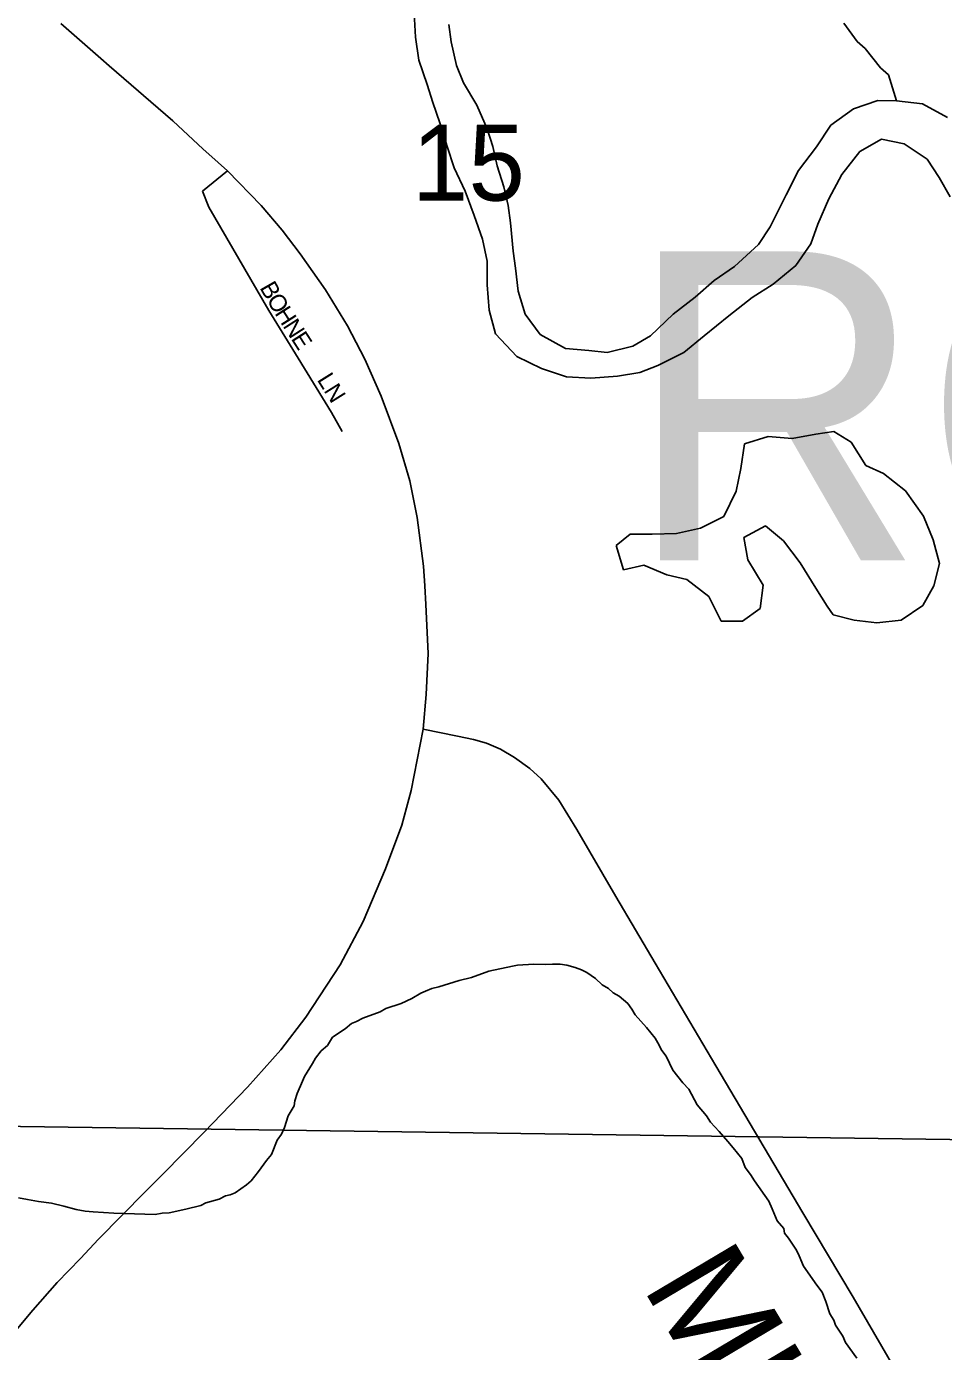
# Model space of a CAD drawing. Extents: x 0 to 34, y -2.3 to 22.
# Drawn here: x 5.851 to 6.357, y 17.221 to 17.952 of the extents above; entities that cross this region are included whole.
import ezdxf

# ---------------------------------------------------------------- set-up
doc = ezdxf.new("R2010")
doc.units = 0
for name, color, linetype in [('GM_X_Major_River', 7, 'Continuous'), ('GM_X_Minor_Lake', 7, 'Continuous'), ('GM_X_Minor_River', 7, 'Continuous'), ('GM_X_Section', 7, 'Continuous'), ('GM_X_Section_Text', 7, 'Continuous'), ('GM_X_Township_Road', 7, 'Continuous'), ('GM_X_Township_Road_Text', 7, 'Continuous'), ('GM_X_Township_Subdivision', 7, 'Continuous'), ('GM_X_Township_Subdivision_Text', 7, 'Continuous'), ('GM_X_Township_Text', 7, 'Continuous'), ('GM_X_US_Route', 7, 'Continuous')]:
    doc.layers.add(name, color=color, linetype=linetype)

msp = doc.modelspace()

# ---------------------------------------------------------------- linework, layer by layer
at = {"layer": 'GM_X_Major_River'}
for p, q in [((6.06492, 17.95936), (6.06566, 17.94603)), ((6.08535, 17.94355), (6.08411, 17.9531)), ((6.06566, 17.94603), (6.06757, 17.93343)), ((6.08839, 17.93053), (6.08535, 17.94355)), ((6.06757, 17.93343), (6.07212, 17.91998)), ((6.09228, 17.92091), (6.08839, 17.93053)), ((6.07212, 17.91998), (6.07524, 17.91001)), ((6.09952, 17.90853), (6.09228, 17.92091)), ((6.07524, 17.91001), (6.07909, 17.89887)), ((6.10521, 17.89544), (6.09952, 17.90853)), ((6.32076, 17.91117), (6.30732, 17.90662)), ((6.33101, 17.91087), (6.32076, 17.91117)), ((6.3454, 17.90931), (6.33101, 17.91087)), ((6.35924, 17.90167), (6.3454, 17.90931)), ((6.30732, 17.90662), (6.29489, 17.89748)), ((6.07909, 17.89887), (6.08327, 17.88582)), ((6.10835, 17.88584), (6.10521, 17.89544)), ((6.29489, 17.89748), (6.28694, 17.88554)), ((6.31081, 17.88294), (6.32279, 17.88982)), ((6.32279, 17.88982), (6.33525, 17.88717)), ((6.33525, 17.88717), (6.34793, 17.87881)), ((6.08327, 17.88582), (6.0871, 17.87392)), ((6.11069, 17.87512), (6.10835, 17.88584)), ((6.28694, 17.88554), (6.27706, 17.87252)), ((6.30093, 17.8703), (6.31081, 17.88294)), ((6.0871, 17.87392), (6.09318, 17.86119)), ((6.11453, 17.8636), (6.11069, 17.87512)), ((6.27706, 17.87252), (6.2702, 17.85904)), ((6.34793, 17.87881), (6.35447, 17.86873)), ((6.2937, 17.85682), (6.30093, 17.8703)), ((6.35447, 17.86873), (6.36061, 17.85791)), ((6.09318, 17.86119), (6.09811, 17.84774)), ((6.11689, 17.85327), (6.11453, 17.8636)), ((6.2702, 17.85904), (6.26132, 17.84142)), ((6.11813, 17.84373), (6.11689, 17.85327)), ((6.28759, 17.84293), (6.2937, 17.85682)), ((6.09811, 17.84774), (6.10266, 17.83467)), ((6.11957, 17.82809), (6.11813, 17.84373)), ((6.28385, 17.83202), (6.28759, 17.84293)), ((6.26132, 17.84142), (6.25496, 17.83172)), ((6.10266, 17.83467), (6.10534, 17.82242)), ((6.12081, 17.81855), (6.11957, 17.82809)), ((6.25496, 17.83172), (6.24168, 17.81957)), ((6.27551, 17.82009), (6.28385, 17.83202)), ((6.10534, 17.82242), (6.10534, 17.8095)), ((6.12233, 17.80596), (6.12081, 17.81855)), ((6.24168, 17.81957), (6.23043, 17.81191)), ((6.26305, 17.80981), (6.27551, 17.82009)), ((6.10534, 17.8095), (6.10644, 17.79539)), ((6.12614, 17.7933), (6.12233, 17.80596)), ((6.23043, 17.81191), (6.2199, 17.80271)), ((6.25144, 17.80255), (6.26305, 17.80981)), ((6.2199, 17.80271), (6.20784, 17.79318)), ((6.23859, 17.79228), (6.25144, 17.80255)), ((6.10644, 17.79539), (6.10986, 17.78236)), ((6.13455, 17.78202), (6.12614, 17.7933)), ((6.20784, 17.79318), (6.19533, 17.78138)), ((6.22497, 17.78127), (6.23859, 17.79228)), ((6.10986, 17.78236), (6.12165, 17.76985)), ((6.14838, 17.77439), (6.13455, 17.78202)), ((6.19533, 17.78138), (6.18566, 17.77558)), ((6.21368, 17.7721), (6.22497, 17.78127)), ((6.12165, 17.76985), (6.13514, 17.76337)), ((6.16127, 17.77325), (6.14838, 17.77439)), ((6.1715, 17.77219), (6.16127, 17.77325)), ((6.18566, 17.77558), (6.1715, 17.77219)), ((6.19941, 17.76491), (6.21368, 17.7721)), ((6.13514, 17.76337), (6.14906, 17.75878)), ((6.18941, 17.76102), (6.19941, 17.76491)), ((6.14906, 17.75878), (6.16234, 17.75801)), ((6.16234, 17.75801), (6.17719, 17.7591)), ((6.17719, 17.7591), (6.18941, 17.76102))]:
    msp.add_line(p, q, dxfattribs=at)
at = {"layer": 'GM_X_Minor_Lake'}
for p, q in [((6.26019, 17.72586), (6.24715, 17.72168)), ((6.27346, 17.72471), (6.26019, 17.72586)), ((6.28645, 17.72699), (6.27346, 17.72471)), ((6.29638, 17.7286), (6.28645, 17.72699)), ((6.30608, 17.72261), (6.29638, 17.7286)), ((6.24715, 17.72168), (6.24523, 17.70805)), ((6.31406, 17.70983), (6.30608, 17.72261)), ((6.24523, 17.70805), (6.24258, 17.69558)), ((6.32381, 17.70536), (6.31406, 17.70983)), ((6.33607, 17.69588), (6.32381, 17.70536)), ((6.24258, 17.69558), (6.23571, 17.68171)), ((6.34592, 17.6819), (6.33607, 17.69588)), ((6.23571, 17.68171), (6.22298, 17.67524)), ((6.35123, 17.66881), (6.34592, 17.6819)), ((6.22298, 17.67524), (6.20959, 17.67221)), ((6.24677, 17.66998), (6.25874, 17.67647)), ((6.25874, 17.67647), (6.26875, 17.66819)), ((6.18412, 17.67181), (6.17634, 17.66558)), ((6.19628, 17.67184), (6.18412, 17.67181)), ((6.20959, 17.67221), (6.19628, 17.67184)), ((6.24907, 17.65774), (6.24677, 17.66998)), ((6.26875, 17.66819), (6.2779, 17.65613)), ((6.35465, 17.65578), (6.35123, 17.66881)), ((6.17634, 17.66558), (6.1805, 17.65215)), ((6.1805, 17.65215), (6.1916, 17.65486)), ((6.1916, 17.65486), (6.20436, 17.64955)), ((6.25739, 17.64381), (6.24907, 17.65774)), ((6.2779, 17.65613), (6.28661, 17.64219)), ((6.35162, 17.64332), (6.35465, 17.65578)), ((6.20436, 17.64955), (6.21531, 17.64694)), ((6.21531, 17.64694), (6.22757, 17.63746)), ((6.25588, 17.63092), (6.25739, 17.64381)), ((6.28661, 17.64219), (6.29277, 17.63212)), ((6.3456, 17.63247), (6.35162, 17.64332)), ((6.22757, 17.63746), (6.23439, 17.62395)), ((6.24617, 17.62398), (6.25588, 17.63092)), ((6.29277, 17.63212), (6.29605, 17.62746)), ((6.33359, 17.62446), (6.3456, 17.63247)), ((6.23439, 17.62395), (6.24617, 17.62398)), ((6.29605, 17.62746), (6.30775, 17.62446)), ((6.30775, 17.62446), (6.32024, 17.62295)), ((6.32024, 17.62295), (6.33359, 17.62446))]:
    msp.add_line(p, q, dxfattribs=at)
at = {"layer": 'GM_X_Minor_River'}
for p, q in [((6.30935, 17.94367), (6.30204, 17.95376)), ((6.31379, 17.93973), (6.30935, 17.94367)), ((6.32223, 17.92922), (6.31379, 17.93973)), ((6.32668, 17.92529), (6.32223, 17.92922)), ((6.33101, 17.91087), (6.32668, 17.92529)), ((6.24715, 17.72168), (6.26019, 17.72586)), ((6.26019, 17.72586), (6.27346, 17.72471)), ((6.27346, 17.72471), (6.28645, 17.72699)), ((6.28645, 17.72699), (6.29638, 17.7286)), ((6.29638, 17.7286), (6.30608, 17.72261)), ((6.24523, 17.70805), (6.24715, 17.72168)), ((6.30608, 17.72261), (6.31406, 17.70983)), ((6.24258, 17.69558), (6.24523, 17.70805)), ((6.31406, 17.70983), (6.32381, 17.70536)), ((6.32381, 17.70536), (6.33607, 17.69588)), ((6.23571, 17.68171), (6.24258, 17.69558)), ((6.33607, 17.69588), (6.34592, 17.6819)), ((6.22298, 17.67524), (6.23571, 17.68171)), ((6.34592, 17.6819), (6.35123, 17.66881)), ((6.20959, 17.67221), (6.22298, 17.67524)), ((6.25874, 17.67647), (6.24677, 17.66998)), ((6.26875, 17.66819), (6.25874, 17.67647)), ((6.17634, 17.66558), (6.18412, 17.67181)), ((6.18412, 17.67181), (6.19628, 17.67184)), ((6.19628, 17.67184), (6.20959, 17.67221)), ((6.24677, 17.66998), (6.24907, 17.65774)), ((6.2779, 17.65613), (6.26875, 17.66819)), ((6.35123, 17.66881), (6.35465, 17.65578)), ((6.1805, 17.65215), (6.17634, 17.66558)), ((6.1916, 17.65486), (6.1805, 17.65215)), ((6.20436, 17.64955), (6.1916, 17.65486)), ((6.24907, 17.65774), (6.25739, 17.64381)), ((6.28661, 17.64219), (6.2779, 17.65613)), ((6.35465, 17.65578), (6.35162, 17.64332)), ((6.21531, 17.64694), (6.20436, 17.64955)), ((6.22757, 17.63746), (6.21531, 17.64694)), ((6.25739, 17.64381), (6.25588, 17.63092)), ((6.29277, 17.63212), (6.28661, 17.64219)), ((6.35162, 17.64332), (6.3456, 17.63247)), ((6.23439, 17.62395), (6.22757, 17.63746)), ((6.25588, 17.63092), (6.24617, 17.62398)), ((6.29605, 17.62746), (6.29277, 17.63212)), ((6.3456, 17.63247), (6.33359, 17.62446)), ((6.24617, 17.62398), (6.23439, 17.62395)), ((6.30775, 17.62446), (6.29605, 17.62746)), ((6.32024, 17.62295), (6.30775, 17.62446)), ((6.33359, 17.62446), (6.32024, 17.62295)), ((6.11924, 17.43353), (6.10624, 17.43088)), ((6.12192, 17.43421), (6.11924, 17.43353)), ((6.13106, 17.43469), (6.12192, 17.43421)), ((6.13751, 17.4345), (6.13106, 17.43469)), ((6.14132, 17.43476), (6.13751, 17.4345)), ((6.1455, 17.43464), (6.14132, 17.43476)), ((6.14928, 17.43414), (6.1455, 17.43464)), ((6.15381, 17.43287), (6.14928, 17.43414)), ((6.09663, 17.42736), (6.08974, 17.42567)), ((6.10624, 17.43088), (6.09663, 17.42736)), ((6.15719, 17.43163), (6.15381, 17.43287)), ((6.16019, 17.43002), (6.15719, 17.43163)), ((6.16504, 17.42684), (6.16019, 17.43002)), ((6.16873, 17.42331), (6.16504, 17.42684)), ((6.06863, 17.41871), (6.06361, 17.41582)), ((6.07132, 17.41977), (6.06863, 17.41871)), ((6.07479, 17.42118), (6.07132, 17.41977)), ((6.07862, 17.42221), (6.07479, 17.42118)), ((6.08974, 17.42567), (6.07862, 17.42221)), ((6.1721, 17.42131), (6.16873, 17.42331)), ((6.17469, 17.41895), (6.1721, 17.42131)), ((6.17805, 17.41695), (6.17469, 17.41895)), ((6.05782, 17.41295), (6.04938, 17.41017)), ((6.06361, 17.41582), (6.05782, 17.41295)), ((6.18288, 17.41301), (6.17805, 17.41695)), ((6.18507, 17.4099), (6.18288, 17.41301)), ((6.03668, 17.40485), (6.03321, 17.40305)), ((6.04628, 17.40836), (6.03668, 17.40485)), ((6.04938, 17.41017), (6.04628, 17.40836)), ((6.18688, 17.40681), (6.18507, 17.4099)), ((6.19314, 17.39978), (6.18688, 17.40681)), ((6.02701, 17.39906), (6.02003, 17.39433)), ((6.03051, 17.402), (6.02701, 17.39906)), ((6.03321, 17.40305), (6.03051, 17.402)), ((6.19791, 17.39394), (6.19314, 17.39978)), ((6.01724, 17.38986), (6.01373, 17.38692)), ((6.02003, 17.39433), (6.01724, 17.38986)), ((6.19935, 17.39124), (6.19791, 17.39394)), ((6.2015, 17.387), (6.19935, 17.39124)), ((6.01057, 17.38284), (6.00896, 17.37985)), ((6.01373, 17.38692), (6.01057, 17.38284)), ((6.20407, 17.38388), (6.2015, 17.387)), ((6.20765, 17.37618), (6.20407, 17.38388)), ((6.00896, 17.37985), (6.00457, 17.37276)), ((6.21315, 17.36918), (6.20765, 17.37618)), ((6.00336, 17.37014), (6.0005, 17.36339)), ((6.00457, 17.37276), (6.00336, 17.37014)), ((6.21647, 17.36566), (6.21315, 17.36918)), ((6.0005, 17.36339), (5.99924, 17.35925)), ((6.22116, 17.35716), (6.21647, 17.36566)), ((5.99878, 17.3566), (5.99558, 17.351)), ((5.99924, 17.35925), (5.99878, 17.3566)), ((6.2263, 17.35093), (6.22116, 17.35716)), ((5.99558, 17.351), (5.99349, 17.34461)), ((6.22848, 17.34745), (6.2263, 17.35093)), ((6.23327, 17.34236), (6.22848, 17.34745)), ((5.99186, 17.34086), (5.98948, 17.33751)), ((5.99349, 17.34461), (5.99186, 17.34086)), ((6.23805, 17.3369), (6.23327, 17.34236)), ((5.98948, 17.33751), (5.98621, 17.32963)), ((6.24099, 17.3334), (6.23805, 17.3369)), ((6.24576, 17.32756), (6.24099, 17.3334)), ((5.98345, 17.32629), (5.9791, 17.32035)), ((5.98621, 17.32963), (5.98345, 17.32629)), ((6.24752, 17.32257), (6.24576, 17.32756)), ((5.9791, 17.32035), (5.97515, 17.31515)), ((6.25044, 17.31868), (6.24752, 17.32257)), ((6.25262, 17.3152), (6.25044, 17.31868)), ((5.97242, 17.31295), (5.96621, 17.30858)), ((5.97515, 17.31515), (5.97242, 17.31295)), ((6.26066, 17.30394), (6.25262, 17.3152)), ((5.85169, 17.30479), (5.84678, 17.3057)), ((5.85775, 17.30385), (5.85169, 17.30479)), ((5.86494, 17.30287), (5.85775, 17.30385)), ((5.87173, 17.30115), (5.86494, 17.30287)), ((5.94738, 17.30155), (5.93896, 17.29952)), ((5.95008, 17.30298), (5.94738, 17.30155)), ((5.95737, 17.30505), (5.95008, 17.30298)), ((5.96084, 17.30684), (5.95737, 17.30505)), ((5.96352, 17.30752), (5.96084, 17.30684)), ((5.96621, 17.30858), (5.96352, 17.30752)), ((6.26243, 17.29971), (6.26066, 17.30394)), ((5.87852, 17.29943), (5.87173, 17.30115)), ((5.88344, 17.29852), (5.87852, 17.29943)), ((5.88798, 17.29801), (5.88344, 17.29852)), ((5.89936, 17.29729), (5.88798, 17.29801)), ((5.92215, 17.2966), (5.89936, 17.29729)), ((5.92597, 17.29725), (5.92215, 17.2966)), ((5.92978, 17.29752), (5.92597, 17.29725)), ((5.93896, 17.29952), (5.92978, 17.29752)), ((6.26528, 17.29317), (6.26243, 17.29971)), ((6.26896, 17.28888), (6.26528, 17.29317)), ((6.26926, 17.28621), (6.26896, 17.28888)), ((6.27147, 17.28349), (6.26926, 17.28621)), ((6.27583, 17.2769), (6.27147, 17.28349)), ((6.27726, 17.27382), (6.27583, 17.2769)), ((6.27976, 17.26804), (6.27726, 17.27382)), ((6.28705, 17.25757), (6.27976, 17.26804)), ((6.28998, 17.25368), (6.28705, 17.25757)), ((6.29212, 17.24868), (6.28998, 17.25368)), ((6.2942, 17.24178), (6.29212, 17.24868)), ((6.29637, 17.2383), (6.2942, 17.24178)), ((6.29744, 17.23561), (6.29637, 17.2383)), ((6.30144, 17.22941), (6.29744, 17.23561)), ((6.30286, 17.22595), (6.30144, 17.22941)), ((6.30907, 17.2174), (6.30286, 17.22595))]:
    msp.add_line(p, q, dxfattribs=at)
at = {"layer": 'GM_X_Section'}
for p, q in [((6.57262, 17.33501), (5.3441, 17.35232)), ((5.3441, 17.35232), (6.57262, 17.33501))]:
    msp.add_line(p, q, dxfattribs=at)
at = {"layer": 'GM_X_Township_Road'}
for p, q in [((6.08886, 17.56054), (6.07, 17.56436)), ((6.09773, 17.55866), (6.08886, 17.56054)), ((6.10481, 17.55663), (6.09773, 17.55866)), ((6.11263, 17.55321), (6.10481, 17.55663)), ((6.12036, 17.54873), (6.11263, 17.55321)), ((6.12875, 17.54271), (6.12036, 17.54873)), ((6.13502, 17.53685), (6.12875, 17.54271)), ((6.14478, 17.5252), (6.13502, 17.53685)), ((6.15472, 17.50892), (6.14478, 17.5252)), ((6.17613, 17.47204), (6.15472, 17.50892)), ((6.19787, 17.43533), (6.17613, 17.47204)), ((6.23141, 17.37866), (6.19787, 17.43533)), ((6.27927, 17.2975), (6.23141, 17.37866)), ((6.30704, 17.25101), (6.27927, 17.2975)), ((6.34367, 17.18816), (6.30704, 17.25101))]:
    msp.add_line(p, q, dxfattribs=at)
at = {"layer": 'GM_X_Township_Subdivision'}
for p, q in [((5.96209, 17.87234), (5.94818, 17.86119)), ((5.94818, 17.86119), (5.95168, 17.85223)), ((5.95168, 17.85223), (5.98483, 17.79524)), ((5.98483, 17.79524), (6.00099, 17.76905)), ((6.00099, 17.76905), (6.01935, 17.739)), ((6.01935, 17.739), (6.02521, 17.72861))]:
    msp.add_line(p, q, dxfattribs=at)
at = {"layer": 'GM_X_US_Route'}
for p, q in [((5.89219, 17.93422), (5.87004, 17.95357)), ((5.89669, 17.93032), (5.89219, 17.93422)), ((5.93179, 17.89984), (5.89669, 17.93032)), ((5.94859, 17.88434), (5.93179, 17.89984)), ((5.95165, 17.88151), (5.94859, 17.88434)), ((5.96209, 17.87234), (5.95165, 17.88151)), ((5.98068, 17.85312), (5.96209, 17.87234)), ((5.99214, 17.83961), (5.98068, 17.85312)), ((6.00216, 17.82658), (5.99214, 17.83961)), ((6.01615, 17.80672), (6.00216, 17.82658)), ((6.02828, 17.78678), (6.01615, 17.80672)), ((6.03773, 17.76846), (6.02828, 17.78678)), ((6.04685, 17.74794), (6.03773, 17.76846)), ((6.05646, 17.72189), (6.04685, 17.74794)), ((6.06264, 17.7013), (6.05646, 17.72189)), ((6.06672, 17.6811), (6.06264, 17.7013)), ((6.07008, 17.65432), (6.06672, 17.6811)), ((6.07078, 17.64347), (6.07008, 17.65432)), ((6.07146, 17.63302), (6.07078, 17.64347)), ((6.07269, 17.60602), (6.07146, 17.63302)), ((6.0716, 17.58341), (6.07269, 17.60602)), ((6.07, 17.56436), (6.0716, 17.58341)), ((6.06329, 17.53043), (6.07, 17.56436)), ((6.05825, 17.51137), (6.06329, 17.53043)), ((6.04922, 17.48726), (6.05825, 17.51137)), ((6.03688, 17.45817), (6.04922, 17.48726)), ((6.02411, 17.43426), (6.03688, 17.45817)), ((6.00518, 17.40542), (6.02411, 17.43426)), ((5.99136, 17.38742), (6.00518, 17.40542)), ((5.97304, 17.36687), (5.99136, 17.38742)), ((5.94907, 17.34202), (5.97304, 17.36687)), ((5.92645, 17.31885), (5.94907, 17.34202)), ((5.91667, 17.30913), (5.92645, 17.31885)), ((5.89095, 17.28297), (5.91667, 17.30913)), ((5.88099, 17.27226), (5.89095, 17.28297)), ((5.86803, 17.25912), (5.88099, 17.27226)), ((5.85464, 17.24373), (5.86803, 17.25912)), ((5.83577, 17.22138), (5.85464, 17.24373))]:
    msp.add_line(p, q, dxfattribs=at)

# ---------------------------------------------------------------- texts
at = {"layer": 'GM_X_Section_Text'}
msp.add_text('15', height=0.041856, rotation=0.00001, dxfattribs=at).set_placement((6.0638, 17.85592))
at = {"layer": 'GM_X_Township_Road_Text'}
msp.add_text('MILLVILLE RD', height=0.0568182, rotation=300.71037, dxfattribs=at).set_placement((6.19033, 17.25686))
at = {"layer": 'GM_X_Township_Subdivision_Text'}
for s, rotation, p in [('B', 299.81943, (5.97952, 17.80788)), ('O', 300.79478, (5.98334, 17.80122)), ('H', 302.58247, (5.98777, 17.79379)), ('N', 302.72917, (5.99228, 17.78675)), ('E', 302.74169, (5.99678, 17.77974)), ('LN', 302.00539, (6.01115, 17.75711))]:
    msp.add_text(s, height=0.00947, rotation=rotation, dxfattribs=at).set_placement(p)
at = {"layer": 'GM_X_Township_Text'}
msp.add_text('ROSS', height=0.170455, rotation=0.00001, dxfattribs=at).set_placement((6.18183, 17.65742))

doc.saveas('drawing.dxf')
